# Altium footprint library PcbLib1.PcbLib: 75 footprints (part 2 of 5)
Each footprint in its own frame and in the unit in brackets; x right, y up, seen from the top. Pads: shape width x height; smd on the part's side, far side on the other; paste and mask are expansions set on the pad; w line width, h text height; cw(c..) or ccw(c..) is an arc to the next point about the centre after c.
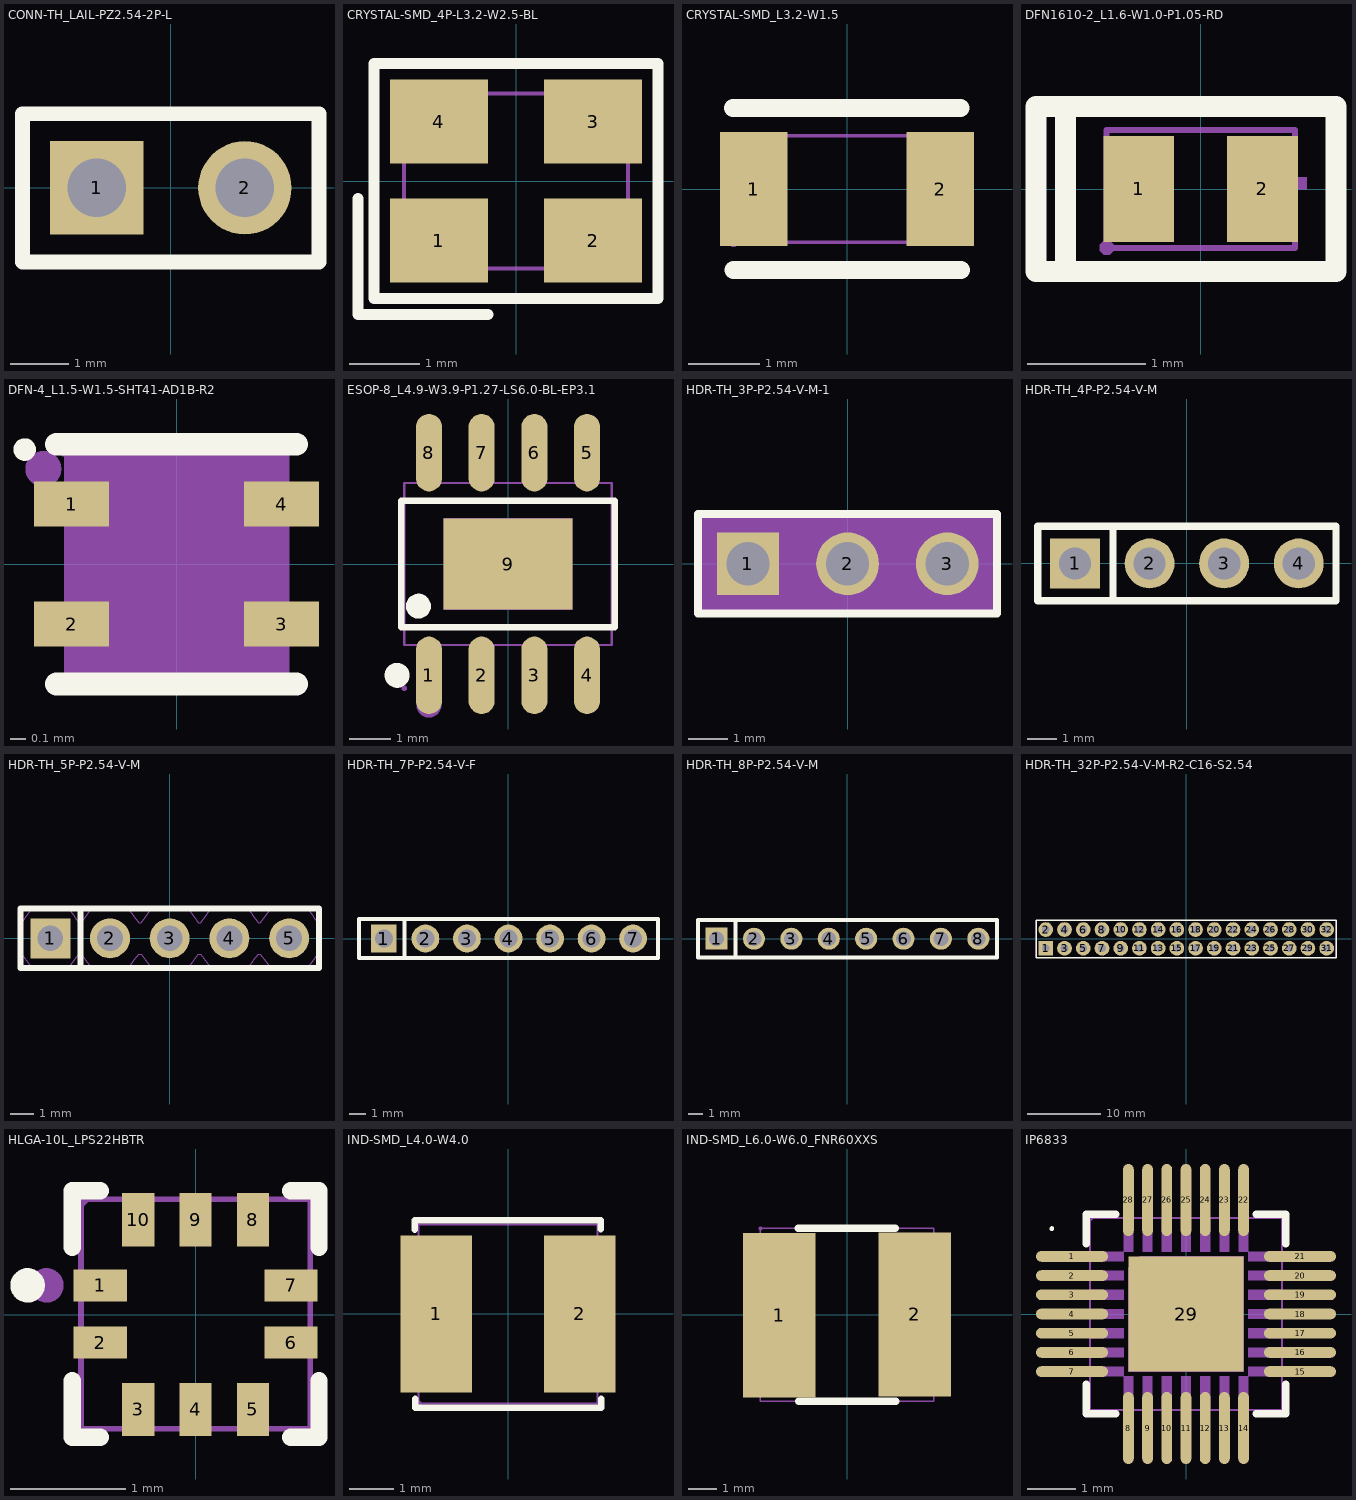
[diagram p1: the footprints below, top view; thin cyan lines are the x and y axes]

## CONN-TH_LAIL-PZ2.54-2P-L [mm]
pads (2):
  rect 1.6x1.6 hole 1 paste-2539.97 mask+0.05: 1(-1.27,0)
  round 1.6 hole 1 paste-2539.97 mask+0.05: 2(1.27,0)
Top Overlay:
  lines w0.254: -2.54,-1.27 2.54,-1.27 2.54,1.27 -2.54,1.27 -2.54,-1.27
Mechanical 6:
  lines w0.051: -2.54,-1.25 2.54,-1.25 2.54,1.25 -2.54,1.25 -2.54,-1.25
Mechanical 8:
  region: -2.48,-1.25 -2.48,-1.275 -2.515,-1.31 -2.565,-1.31 -2.6,-1.275 -2.6,-1.25 -2.6,-1.225 -2.565,-1.19 -2.515,-1.19 -2.48,-1.225 -2.48,-1.25
Mechanical 9:
  region: 0.95,0.32 1.59,0.32 1.59,-0.32 0.95,-0.32
  region: -1.59,0.32 -0.95,0.32 -0.95,-0.32 -1.59,-0.32

## CRYSTAL-SMD_4P-L3.2-W2.5-BL [mm]
pads (4):
  rect 1.4x1.2 smd: 1(-1.1,-0.85) 2(1.1,-0.85) 3(1.1,0.85) 4(-1.1,0.85)
Top Overlay:
  lines w0.152: -2.257,-0.25 -2.257,-1.907 -0.4,-1.907 ; -2.029,-1.678 2.029,-1.678 2.029,1.679 -2.029,1.679 -2.029,-1.678
Mechanical 2:
  circle w0.254: c-1.27,-0.889 r0.127
Mechanical 6:
  lines w0.051: -1.6,-1.25 1.6,-1.25 1.6,1.25 -1.6,1.25 -1.6,-1.25
Mechanical 8:
  region: -1.54,-1.25 -1.54,-1.275 -1.575,-1.31 -1.625,-1.31 -1.66,-1.275 -1.66,-1.25 -1.66,-1.225 -1.625,-1.19 -1.575,-1.19 -1.54,-1.225 -1.54,-1.25
Mechanical 9:
  region: -1.5,-0.35 -0.6,-0.35 -0.6,-1.15 -1.5,-1.15
  region: 0.6,-0.35 1.5,-0.35 1.5,-1.15 0.6,-1.15
  region: 0.6,1.15 1.5,1.15 1.5,0.35 0.6,0.35
  region: -1.5,1.15 -0.6,1.15 -0.6,0.35 -1.5,0.35

## CRYSTAL-SMD_L3.2-W1.5 [mm]
pads (2):
  rect 0.95x1.6 smd: 1(-1.308,0) 2(1.308,0)
Top Overlay:
  lines w0.254: -1.603,1.14 1.597,1.14 ; -1.597,-1.14 1.603,-1.14
Mechanical 6:
  lines w0.051: -1.597,-0.75 1.603,-0.75 1.603,0.75 -1.597,0.75 -1.597,-0.75
Mechanical 8:
  region: -1.537,-0.75 -1.537,-0.775 -1.573,-0.81 -1.622,-0.81 -1.657,-0.775 -1.657,-0.75 -1.657,-0.725 -1.622,-0.69 -1.573,-0.69 -1.537,-0.725 -1.537,-0.75
Mechanical 9:
  region: -1.598,-0.65 -1.598,0.65 -0.847,0.65 -0.847,-0.65
  region: 0.853,-0.65 0.853,0.65 1.603,0.65 1.603,-0.65

## DFN1610-2_L1.6-W1.0-P1.05-RD [mm]
pads (2):
  rect 0.6x0.9 smd: 1(-0.525,0) 2(0.525,0)
Top Overlay:
  lines w0.178: -1.15,-0.7 -1.15,0.7 ; -1.4,-0.7 -1.4,0.7 1.15,0.7 1.15,-0.7 -1.4,-0.7
Mechanical 2:
  region: -0.8,0.1 -0.3,0.1 -0.3,0 -0.8,0
  region: 0.4,0.1 0.9,0.1 0.9,0 0.4,0
  region: 0.6,-0.2 0.6,0.3 0.7,0.3 0.7,-0.2
Mechanical 6:
  lines w0.051: -0.8,-0.5 -0.8,0.5 0.8,0.5 0.8,-0.5 -0.8,-0.5
Mechanical 8:
  region: -0.74,-0.5 -0.74,-0.525 -0.775,-0.56 -0.825,-0.56 -0.86,-0.525 -0.86,-0.5 -0.86,-0.475 -0.825,-0.44 -0.775,-0.44 -0.74,-0.475 -0.74,-0.5
Mechanical 9:
  region: -0.35,0.4 -0.35,-0.4 -0.7,-0.4 -0.7,0.4
  region: 0.7,0.4 0.7,-0.4 0.35,-0.4 0.35,0.4

## DFN-4_L1.5-W1.5-SHT41-AD1B-R2 [mm]
pads (4):
  rect 0.5x0.3 smd paste+0 mask+0.051: 1(-0.7,0.4) 2(-0.7,-0.4) 3(0.7,-0.4) 4(0.7,0.4)
Top Overlay:
  circle w0.075: c-1.013,0.765 r0.038
  lines w0.152: -0.8,-0.8 0.8,-0.8 ; -0.8,0.8 0.8,0.8
Mechanical 5:
  circle w0.12: c-0.889,0.635 r0.06
Mechanical 9:
  region: -0.75,-0.75 -0.75,0.75 0.75,0.75 0.75,-0.75
Mechanical 11:
  region: -0.72,0.75 -0.72,0.738 -0.738,0.72 -0.762,0.72 -0.78,0.738 -0.78,0.75 -0.78,0.762 -0.762,0.78 -0.738,0.78 -0.72,0.762 -0.72,0.75
Mechanical 12:
  region: -0.45,0.505 -0.45,0.55 -0.68,0.55 -0.68,0.505 -0.75,0.505 -0.75,0.295 -0.68,0.295 -0.68,0.25 -0.45,0.25 -0.45,0.295
  region: -0.45,-0.295 -0.45,-0.25 -0.68,-0.25 -0.68,-0.295 -0.75,-0.295 -0.75,-0.505 -0.68,-0.505 -0.68,-0.55 -0.45,-0.55 -0.45,-0.505
  region: 0.45,-0.505 0.45,-0.55 0.68,-0.55 0.68,-0.505 0.75,-0.505 0.75,-0.295 0.68,-0.295 0.68,-0.25 0.45,-0.25 0.45,-0.295
  region: 0.45,0.295 0.45,0.25 0.68,0.25 0.68,0.295 0.75,0.295 0.75,0.505 0.68,0.505 0.68,0.55 0.45,0.55 0.45,0.505

## ESOP-8_L4.9-W3.9-P1.27-LS6.0-BL-EP3.1 [mm]
pads (9):
  oval 0.63x1.865 smd: 1(-1.905,-2.682) 2(-0.635,-2.682) 3(0.635,-2.682) 4(1.905,-2.682) 5(1.905,2.682) 6(0.635,2.682) 7(-0.635,2.682) 8(-1.905,2.682)
  rect 3.1x2.2 smd paste+0 mask+0.05: 9(0,0)
Top Overlay:
  circle w0.3: c-2.159,-1.016 r0.15
  circle w0.3: c-2.672,-2.682 r0.15
  lines w0.152: -2.576,-1.521 2.576,-1.521 2.576,1.521 -2.576,1.521 -2.576,-1.521
Mechanical 4:
  circle w0.3: c-1.905,-3.4 r0.15
Mechanical 7:
  lines w0.051: -2.5,-1.95 2.5,-1.95 2.5,1.95 -2.5,1.95 -2.5,-1.95
Mechanical 8:
  region: 1.695,1.94 1.695,2.175 2.115,2.175 2.115,1.94
  region: 0.425,1.94 0.425,2.175 0.845,2.175 0.845,1.94
  region: -0.845,1.94 -0.845,2.175 -0.425,2.175 -0.425,1.94
  region: -2.115,1.94 -2.115,2.175 -1.695,2.175 -1.695,1.94
  region: 1.695,-2.175 1.695,-1.94 2.115,-1.94 2.115,-2.175
  region: 0.425,-2.175 0.425,-1.94 0.845,-1.94 0.845,-2.175
  region: -0.845,-2.175 -0.845,-1.94 -0.425,-1.94 -0.425,-2.175
  region: -2.115,-2.175 -2.115,-1.94 -1.695,-1.94 -1.695,-2.175
Mechanical 9:
  region: -2.44,-3 -2.44,-3.025 -2.475,-3.06 -2.525,-3.06 -2.56,-3.025 -2.56,-3 -2.56,-2.975 -2.525,-2.94 -2.475,-2.94 -2.44,-2.975 -2.44,-3
Mechanical 10:
  region: -1.55,1.1 1.55,1.1 1.55,-1.1 -1.55,-1.1
  region: 1.695,2.165 1.695,3 2.115,3 2.115,2.165
  region: 0.425,2.165 0.425,3 0.845,3 0.845,2.165
  region: -0.845,2.165 -0.845,3 -0.425,3 -0.425,2.165
  region: -2.115,2.165 -2.115,3 -1.695,3 -1.695,2.165
  region: 1.695,-3 1.695,-2.165 2.115,-2.165 2.115,-3
  region: 0.425,-3 0.425,-2.165 0.845,-2.165 0.845,-3
  region: -0.845,-3 -0.845,-2.165 -0.425,-2.165 -0.425,-3
  region: -2.115,-3 -2.115,-2.165 -1.695,-2.165 -1.695,-3

## HDR-TH_3P-P2.54-V-M-1 [mm]
pads (3):
  rect 1.575x1.6 hole 1.1 paste-2539.97 mask+0.05: 1(-2.54,0)
  round 1.6 hole 1.1 paste-2539.97 mask+0.05: 2(0,0) 3(2.54,0)
Top Overlay:
  lines w0.203: -3.81,-1.27 3.81,-1.27 3.81,1.27 -1.905,1.27 -3.81,1.27 -3.81,-1.27
Mechanical 9:
  region: -3.81,-1.25 -3.81,1.25 3.81,1.25 3.81,-1.25
Mechanical 11:
  region: -3.78,-1.25 -3.78,-1.262 -3.798,-1.28 -3.822,-1.28 -3.84,-1.262 -3.84,-1.25 -3.84,-1.238 -3.822,-1.22 -3.798,-1.22 -3.78,-1.238 -3.78,-1.25
Mechanical 12:
  region: -2.86,0.32 -2.22,0.32 -2.22,-0.32 -2.86,-0.32
  region: -0.32,0.32 0.32,0.32 0.32,-0.32 -0.32,-0.32
  region: 2.22,0.32 2.86,0.32 2.86,-0.32 2.22,-0.32

## HDR-TH_4P-P2.54-V-M [mm]
pads (4):
  rect 1.7x1.7 hole 1.1: 1(-3.81,0)
  round 1.7 hole 1.1: 2(-1.27,0) 3(1.27,0) 4(3.81,0)
Top Overlay:
  lines w0.254: -2.516,-1.27 -2.516,1.27 ; -2.516,1.27 5.08,1.27 5.08,-1.27 -5.08,-1.27 -5.08,1.27 -2.516,1.27
Mechanical 6:
  lines w0.051: -5.08,-1.25 -5.08,1.25 5.08,1.25 5.08,-1.25 -5.08,-1.25
Mechanical 8:
  region: -5.02,-1.25 -5.02,-1.275 -5.055,-1.31 -5.105,-1.31 -5.14,-1.275 -5.14,-1.25 -5.14,-1.225 -5.105,-1.19 -5.055,-1.19 -5.02,-1.225 -5.02,-1.25
Mechanical 9:
  region: -4.13,0.32 -3.49,0.32 -3.49,-0.32 -4.13,-0.32
  region: -1.59,0.32 -0.95,0.32 -0.95,-0.32 -1.59,-0.32
  region: 0.95,0.32 1.59,0.32 1.59,-0.32 0.95,-0.32
  region: 3.49,0.32 4.13,0.32 4.13,-0.32 3.49,-0.32

## HDR-TH_5P-P2.54-V-M [mm]
pads (5):
  rect 1.7x1.7 hole 1.1: 1(-5.08,0)
  round 1.7 hole 1.1: 2(-2.54,0) 3(0,0) 4(2.54,0) 5(5.08,0)
Top Overlay:
  lines w0.254: -3.786,-1.27 -3.786,1.27 ; -6.35,-1.27 6.35,-1.27 6.35,1.27 -6.35,1.27 -6.35,-1.27
Mechanical 6:
  lines w0.051: -6.35,-0.67 -6.35,0.67 -6.299,0.67 -6.028,1.032 -5.85,1.27 -4.31,1.27 -4.149,1.059 -4.048,0.925 -4.017,0.884 -3.86,0.67 -3.76,0.67 -3.31,1.27 -1.77,1.27 -1.631,1.088 -1.546,0.976 -1.459,0.859 -1.436,0.827 -1.417,0.801 -1.32,0.67 -1.22,0.67 -0.77,1.27 0.77,1.27 0.867,1.143 1.01,0.955 1.108,0.822 1.136,0.783 1.22,0.67 1.32,0.67 1.77,1.27 3.31,1.27 3.458,1.076 3.533,0.979 3.76,0.67 3.86,0.67 4.311,1.27 5.85,1.27 6.079,0.97 6.112,0.925 6.3,0.67 6.35,0.67 6.35,-0.67 6.3,-0.67 6.075,-0.976 5.85,-1.27 4.31,-1.27 3.86,-0.67 3.759,-0.67 3.581,-0.913 3.545,-0.963 3.51,-1.009 3.31,-1.271 1.77,-1.27 1.32,-0.67 1.22,-0.67 1.02,-0.942 0.992,-0.98 0.77,-1.27 -0.77,-1.27 -1.22,-0.67 -1.32,-0.67 -1.503,-0.919 -1.542,-0.972 -1.77,-1.27 -3.31,-1.27 -3.76,-0.67 -3.86,-0.67 -4.077,-0.965 -4.31,-1.27 -5.85,-1.27 -6.3,-0.67 -6.35,-0.67 -6.35,-0.67 ; -6.35,-0.67 -6.35,-0.67
Mechanical 8:
  region: -6.29,-1.271 -6.29,-1.296 -6.325,-1.331 -6.375,-1.331 -6.41,-1.296 -6.41,-1.271 -6.41,-1.246 -6.375,-1.211 -6.325,-1.211 -6.29,-1.246 -6.29,-1.271
Mechanical 9:
  region: 4.76,0.32 5.4,0.32 5.4,-0.32 4.76,-0.32
  region: 2.22,0.32 2.86,0.32 2.86,-0.32 2.22,-0.32
  region: -0.32,0.32 0.32,0.32 0.32,-0.32 -0.32,-0.32
  region: -2.86,0.32 -2.22,0.32 -2.22,-0.32 -2.86,-0.32
  region: -5.4,0.32 -4.76,0.32 -4.76,-0.32 -5.4,-0.32

## HDR-TH_7P-P2.54-V-F [mm]
pads (7):
  rect 1.575x1.7 hole 1.1: 1(-7.62,0)
  round 1.7 hole 1.1: 2(-5.08,0) 3(-2.54,0) 4(0,0) 5(2.54,0) 6(5.08,0) 7(7.62,0)
Top Overlay:
  lines w0.254: -6.35,-1.143 -6.35,1.143 ; -9.13,-1.2 -9.13,1.2 9.13,1.2 9.13,-1.2 -9.13,-1.2
Mechanical 6:
  lines w0.051: -9.14,-1.25 9.14,-1.25 9.14,1.25 -9.14,1.25 -9.14,-1.25
Mechanical 8:
  region: -9.08,-1.25 -9.08,-1.275 -9.115,-1.31 -9.165,-1.31 -9.2,-1.275 -9.2,-1.25 -9.2,-1.225 -9.165,-1.19 -9.115,-1.19 -9.08,-1.225 -9.08,-1.25
Mechanical 9:
  region: 7.3,0.2 7.94,0.2 7.94,-0.2 7.3,-0.2
  region: 4.76,0.2 5.4,0.2 5.4,-0.2 4.76,-0.2
  region: 2.22,0.2 2.86,0.2 2.86,-0.2 2.22,-0.2
  region: -0.32,0.2 0.32,0.2 0.32,-0.2 -0.32,-0.2
  region: -2.86,0.2 -2.22,0.2 -2.22,-0.2 -2.86,-0.2
  region: -5.4,0.2 -4.76,0.2 -4.76,-0.2 -5.4,-0.2
  region: -7.94,-0.2 -7.94,0.2 -7.3,0.2 -7.3,-0.2

## HDR-TH_8P-P2.54-V-M [mm]
pads (8):
  rect 1.5x1.5 hole 1: 1(-8.89,0)
  round 1.5 hole 1: 2(-6.35,0) 3(-3.81,0) 4(-1.27,0) 5(1.27,0) 6(3.81,0) 7(6.35,0) 8(8.89,0)
Top Overlay:
  lines w0.254: -7.596,-1.27 -7.596,1.27 ; -10.16,-1.27 -10.16,1.27 10.16,1.27 10.16,-1.27 -10.16,-1.27
Mechanical 6:
  lines w0.051: -10.16,-1.25 10.16,-1.25 10.16,1.25 -10.16,1.25 -10.16,-1.25
Mechanical 8:
  region: -10.1,-1.25 -10.1,-1.275 -10.135,-1.31 -10.185,-1.31 -10.22,-1.275 -10.22,-1.25 -10.22,-1.225 -10.185,-1.19 -10.135,-1.19 -10.1,-1.225 -10.1,-1.25
Mechanical 9:
  region: 8.57,0.32 9.21,0.32 9.21,-0.32 8.57,-0.32
  region: 6.03,0.32 6.67,0.32 6.67,-0.32 6.03,-0.32
  region: 3.49,0.32 4.13,0.32 4.13,-0.32 3.49,-0.32
  region: 0.95,0.32 1.59,0.32 1.59,-0.32 0.95,-0.32
  region: -1.59,0.32 -0.95,0.32 -0.95,-0.32 -1.59,-0.32
  region: -4.13,0.32 -3.49,0.32 -3.49,-0.32 -4.13,-0.32
  region: -6.67,0.32 -6.03,0.32 -6.03,-0.32 -6.67,-0.32
  region: -9.21,0.32 -8.57,0.32 -8.57,-0.32 -9.21,-0.32

## HDR-TH_32P-P2.54-V-M-R2-C16-S2.54 [mm]
pads (32):
  rect 2x2 hole 1.05: 1(-19.05,-1.27)
  round 2 hole 1.05: 2(-19.05,1.27) 3(-16.51,-1.27) 4(-16.51,1.27) 5(-13.97,-1.27) 6(-13.97,1.27) 7(-11.43,-1.27) 8(-11.43,1.27) 9(-8.89,-1.27) 10(-8.89,1.27) 11(-6.35,-1.27) 12(-6.35,1.27) 13(-3.81,-1.27) 14(-3.81,1.27) 15(-1.27,-1.27) 16(-1.27,1.27) 17(1.27,-1.27) 18(1.27,1.27) 19(3.81,-1.27) 20(3.81,1.27) 21(6.35,-1.27) 22(6.35,1.27) 23(8.89,-1.27) 24(8.89,1.27) 25(11.43,-1.27) 26(11.43,1.27) 27(13.97,-1.27) 28(13.97,1.27) 29(16.51,-1.27) 30(16.51,1.27) 31(19.05,-1.27) 32(19.05,1.27)
Top Overlay:
  lines w0.203: -20.32,-2.54 -20.32,2.54 20.32,2.54 20.32,-2.54 -20.32,-2.54
Mechanical 6:
  lines w0.051: -20.32,-2.5 -20.32,2.5 20.32,2.5 20.32,-2.5 -20.32,-2.5
Mechanical 8:
  region: -20.26,-2.5 -20.26,-2.525 -20.295,-2.56 -20.345,-2.56 -20.38,-2.525 -20.38,-2.5 -20.38,-2.475 -20.345,-2.44 -20.295,-2.44 -20.26,-2.475 -20.26,-2.5
Mechanical 9:
  drawing of 32 lines, arcs and shapes, not listed

## HLGA-10L_LPS22HBTR [mm]
pads (10):
  rect 0.465x0.28 smd: 1(-0.832,0.255) 2(-0.832,-0.245) 6(0.832,-0.245) 7(0.832,0.255)
  rect 0.28x0.465 smd: 3(-0.5,-0.827) 4(0,-0.827) 5(0.5,-0.827) 8(0.5,0.827) 9(0,0.827) 10(-0.5,0.827)
Top Overlay:
  circle w0.15: c-1.465,0.255 r0.075
  lines w0.152: -1.076,-0.576 -1.076,-1.071 -0.831,-1.071 ; -1.076,0.585 -1.076,1.081 -0.831,1.081 ; 0.831,-1.071 1.076,-1.071 1.076,-0.576 ; 0.831,1.081 1.076,1.081 1.076,0.585
Mechanical 2:
  circle w0.15: c-1.3,0.255 r0.075
Mechanical 6:
  lines w0.051: -1,-0.995 -1,1.005 1,1.005 1,-0.995 -1,-0.995
Mechanical 8:
  region: -0.94,1.005 -0.94,0.98 -0.975,0.945 -1.025,0.945 -1.06,0.98 -1.06,1.005 -1.06,1.03 -1.025,1.065 -0.975,1.065 -0.94,1.03 -0.94,1.005
Mechanical 9:
  region: -0.625,0.63 -0.375,0.63 -0.375,0.905 -0.625,0.905
  region: -0.125,0.63 0.125,0.63 0.125,0.905 -0.125,0.905
  region: 0.375,0.63 0.625,0.63 0.625,0.905 0.375,0.905
  region: 0.9,0.38 0.625,0.38 0.625,0.13 0.9,0.13
  region: 0.9,-0.12 0.625,-0.12 0.625,-0.37 0.9,-0.37
  region: 0.375,-0.62 0.625,-0.62 0.625,-0.895 0.375,-0.895
  region: -0.125,-0.62 0.125,-0.62 0.125,-0.895 -0.125,-0.895
  region: -0.625,-0.62 -0.375,-0.62 -0.375,-0.895 -0.625,-0.895
  region: -0.9,-0.12 -0.625,-0.12 -0.625,-0.37 -0.9,-0.37
  region: -0.9,0.38 -0.712,0.38 -0.625,0.305 -0.625,0.13 -0.9,0.13

## IND-SMD_L4.0-W4.0 [mm]
pads (2):
  rect 1.6x3.5 smd: 1(-1.6,0) 2(1.6,0)
Top Overlay:
  lines w0.15: -2.08,1.88 -2.083,2.095 2.07,2.095 2.07,1.9 ; -2.07,-1.89 -2.07,-2.096 2.082,-2.096 2.08,-1.9
Mechanical 6:
  lines w0.051: -2,-2 -2,2 2,2 2,-2 -2,-2
Mechanical 8:
  region: -1.94,-2 -1.94,-2.025 -1.975,-2.06 -2.025,-2.06 -2.06,-2.025 -2.06,-2 -2.06,-1.975 -2.025,-1.94 -1.975,-1.94 -1.94,-1.975 -1.94,-2
Mechanical 9:
  region: 1.05,1.65 2,1.65 2,-1.65 1.05,-1.65
  region: -2,1.65 -1.05,1.65 -1.05,-1.65 -2,-1.65

## IND-SMD_L6.0-W6.0_FNR60XXS [mm]
pads (2):
  rect 2.5x5.7 smd: 1(-2.35,-0.013) 2(2.35,0.013)
Top Overlay:
  lines w0.254: -1.693,3 1.671,3 ; -1.671,-3 1.693,-3
Mechanical 6:
  lines w0.051: -3,-3 3,-3 3,3 -3,3 -3,-3
Mechanical 8:
  region: -2.94,3 -2.94,2.975 -2.975,2.94 -3.025,2.94 -3.06,2.975 -3.06,3 -3.06,3.025 -3.025,3.06 -2.975,3.06 -2.94,3.025 -2.94,3
Mechanical 9:
  region: -1.45,2.437 -1.45,-2.463 -3,-2.463 -3,2.437
  region: 1.45,-2.437 1.45,2.463 3,2.463 3,-2.437

## IP6833 [mil]
pads (29):
  oval 59x8.82 smd paste+0 mask+2: 1(-93.49,47.24) 2(-93.5,31.5) 3(-93.5,15.75) 4(-93.5,0) 5(-93.5,-15.75) 6(-93.5,-31.5) 7(-93.5,-47.24)
  oval 8.82x59 smd paste+0 mask+2: 8(-47.24,-93.5)
  oval 8.82x59 smd paste-99999 mask+2: 9(-31.5,-93.5) 10(-15.75,-93.5) 11(0,-93.5) 12(15.75,-93.5) 13(31.5,-93.5) 14(47.24,-93.5) 22(47.24,93.5) 23(31.5,93.5) 24(15.75,93.5) 25(0,93.5) 26(-15.75,93.5) 27(-31.5,93.5) 28(-47.24,93.5)
  oval 59x8.82 smd paste-99999 mask+2: 15(93.5,-47.24) 16(93.5,-31.5) 17(93.5,-15.75) 18(93.5,0) 19(93.5,15.75) 20(93.5,31.5) 21(93.49,47.24)
  rect 94.49x94.49 smd paste-99999 mask+2: 29(0,0)
Top Overlay:
  circle w1.97: c-110,70 r0.98
  lines w6: -81.74,-57.65 -81.74,-81.74 -57.65,-81.74 ; -81.74,57.65 -81.74,81.74 -57.65,81.74 ; 57.65,-81.74 81.74,-81.74 81.74,-57.65 ; 57.65,81.74 81.74,81.74 81.74,57.65
Mechanical 6:
  circle w1.97: c-105.15,47.24 r0.98
Mechanical 7:
  lines w2: -78.74,-78.74 78.74,-78.74 78.74,78.74 -78.74,78.74 -78.74,-78.74
Mechanical 8:
  region: -76.38,78.74 -76.38,77.76 -77.76,76.38 -79.72,76.38 -81.1,77.76 -81.1,78.74 -81.1,79.72 -79.72,81.1 -77.76,81.1 -76.38,79.72 -76.38,78.74
Mechanical 9:
  region: -78.74,43.31 -51.18,43.31 -51.18,51.18 -78.74,51.18
  region: -78.74,27.56 -51.18,27.56 -51.18,35.43 -78.74,35.43
  region: -78.74,11.81 -51.18,11.81 -51.18,19.68 -78.74,19.68
  region: -78.74,-3.94 -51.18,-3.94 -51.18,3.94 -78.74,3.94
  region: -78.74,-19.68 -51.18,-19.68 -51.18,-11.81 -78.74,-11.81
  region: -78.74,-35.43 -51.18,-35.43 -51.18,-27.56 -78.74,-27.56
  region: -78.74,-51.18 -51.18,-51.18 -51.18,-43.31 -78.74,-43.31
  region: -51.18,-78.74 -43.31,-78.74 -43.31,-51.18 -51.18,-51.18
  region: -35.43,-78.74 -27.56,-78.74 -27.56,-51.18 -35.43,-51.18
  region: -19.68,-78.74 -11.81,-78.74 -11.81,-51.18 -19.68,-51.18
  region: -3.94,-78.74 3.94,-78.74 3.94,-51.18 -3.94,-51.18
  region: 11.81,-78.74 19.68,-78.74 19.68,-51.18 11.81,-51.18
  region: 27.56,-78.74 35.43,-78.74 35.43,-51.18 27.56,-51.18
  region: 43.31,-78.74 51.18,-78.74 51.18,-51.18 43.31,-51.18
  region: 78.74,-51.18 51.18,-51.18 51.18,-43.31 78.74,-43.31
  region: 78.74,-35.43 51.18,-35.43 51.18,-27.56 78.74,-27.56
  region: 78.74,-19.68 51.18,-19.68 51.18,-11.81 78.74,-11.81
  region: 78.74,-3.94 51.18,-3.94 51.18,3.94 78.74,3.94
  region: 78.74,11.81 51.18,11.81 51.18,19.68 78.74,19.68
  region: 78.74,27.56 51.18,27.56 51.18,35.43 78.74,35.43
  region: 78.74,43.31 51.18,43.31 51.18,51.18 78.74,51.18
  region: 43.31,78.74 51.18,78.74 51.18,51.18 43.31,51.18
  region: 27.56,78.74 35.43,78.74 35.43,51.18 27.56,51.18
  region: 11.81,78.74 19.68,78.74 19.68,51.18 11.81,51.18
  region: -3.94,78.74 3.94,78.74 3.94,51.18 -3.94,51.18
  region: -19.68,78.74 -11.81,78.74 -11.81,51.18 -19.68,51.18
  region: -35.43,78.74 -27.56,78.74 -27.56,51.18 -35.43,51.18
  region: -51.18,78.74 -43.31,78.74 -43.31,51.18 -51.18,51.18
  region: -37.8,47.24 47.24,47.24 47.24,-47.24 -47.24,-47.24 -47.24,37.8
